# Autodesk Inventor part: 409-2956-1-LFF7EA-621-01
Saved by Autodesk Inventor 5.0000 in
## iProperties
Created: 2010-06
Part Number: 409-2956-1-LFF7EA-621-01
Cost Center: 0 lbmass
Material: A36 STEEL PLATE
Document SubType Name: Sheet Metal
Designer: S. Boerckel
Authority: 0 in^3
Mass: 7613.93 g
Surface Area: 1011.44 cm^2
Volume: 968.693 cm^3
Density: 7.86 g/cm^3
Flat Pattern Width: 15.24 cm
Flat Pattern Length: 25.4 cm
Flat Pattern Area: 387.096 cm^2
Sheet Metal Rule: 1" HR PLATE
Sheet Metal Width: 10.0000 in
Sheet Metal Length: 50.0000 in^2
Description: STAINER FOOT PLATE
User Status: BURN
SaveDate: 2008-01-15
SaveTime: 10:24
FileName: Sheet Metal
Wide: =<Flat Pattern Width>cm
Length: =<Flat Pattern Length>cm
Thickness: 1.0000 in
SMR: =<Sheet Metal Rule> - <Material>
Author: S. Boerckel
Revision Number: 0
Subject: DEMIN WATER FORWARDING PUMP SKID-7EA
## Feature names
1. Hole1
2. Hole2
3. Plate1
